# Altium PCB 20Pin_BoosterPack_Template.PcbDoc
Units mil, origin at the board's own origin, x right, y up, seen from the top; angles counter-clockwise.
Board outline 2000 x 1700 mil, 2 copper layers (Top Layer, Bottom Layer), stack 62 mil thick; 2 components, 20 nets, 20 pads, 0 vias.
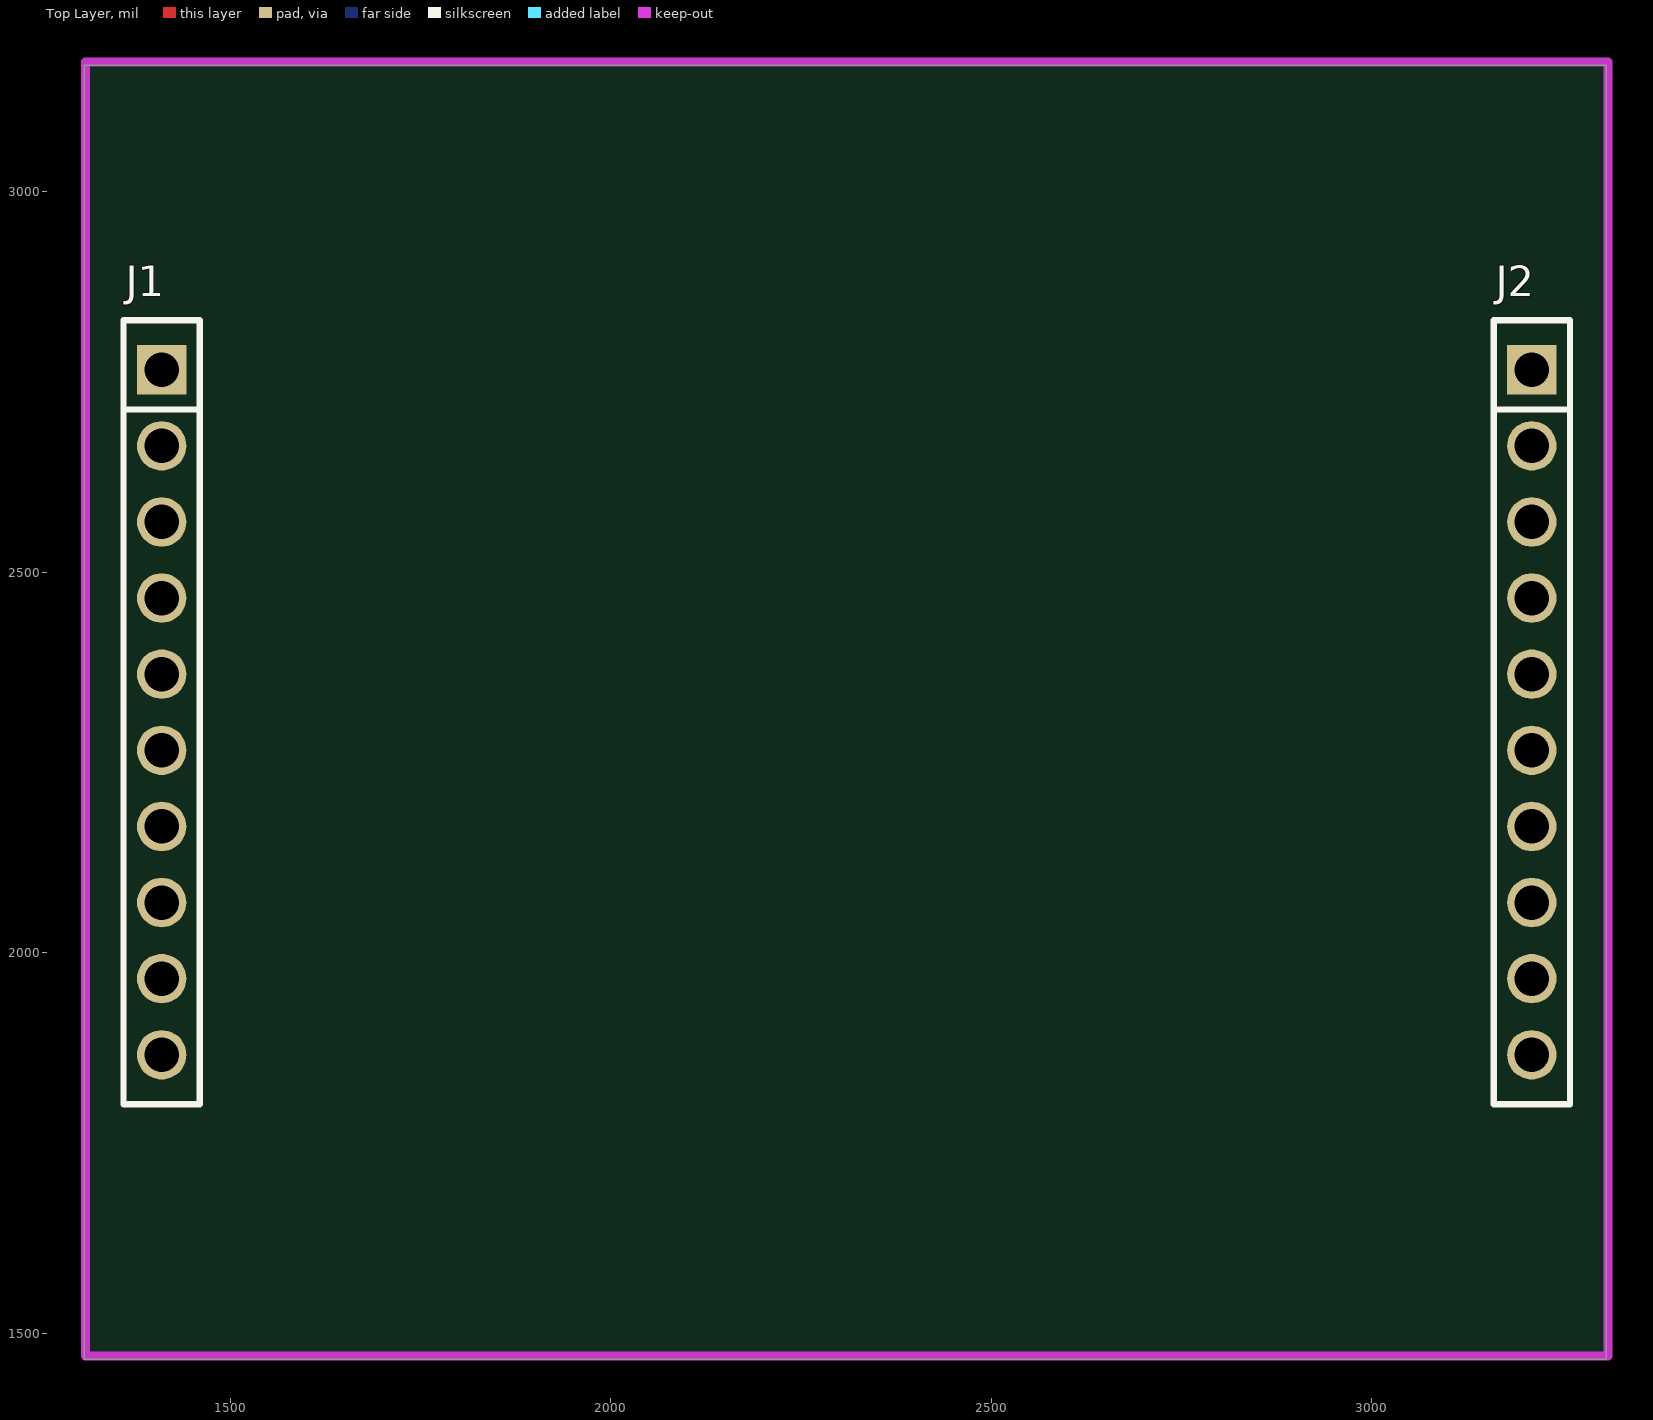
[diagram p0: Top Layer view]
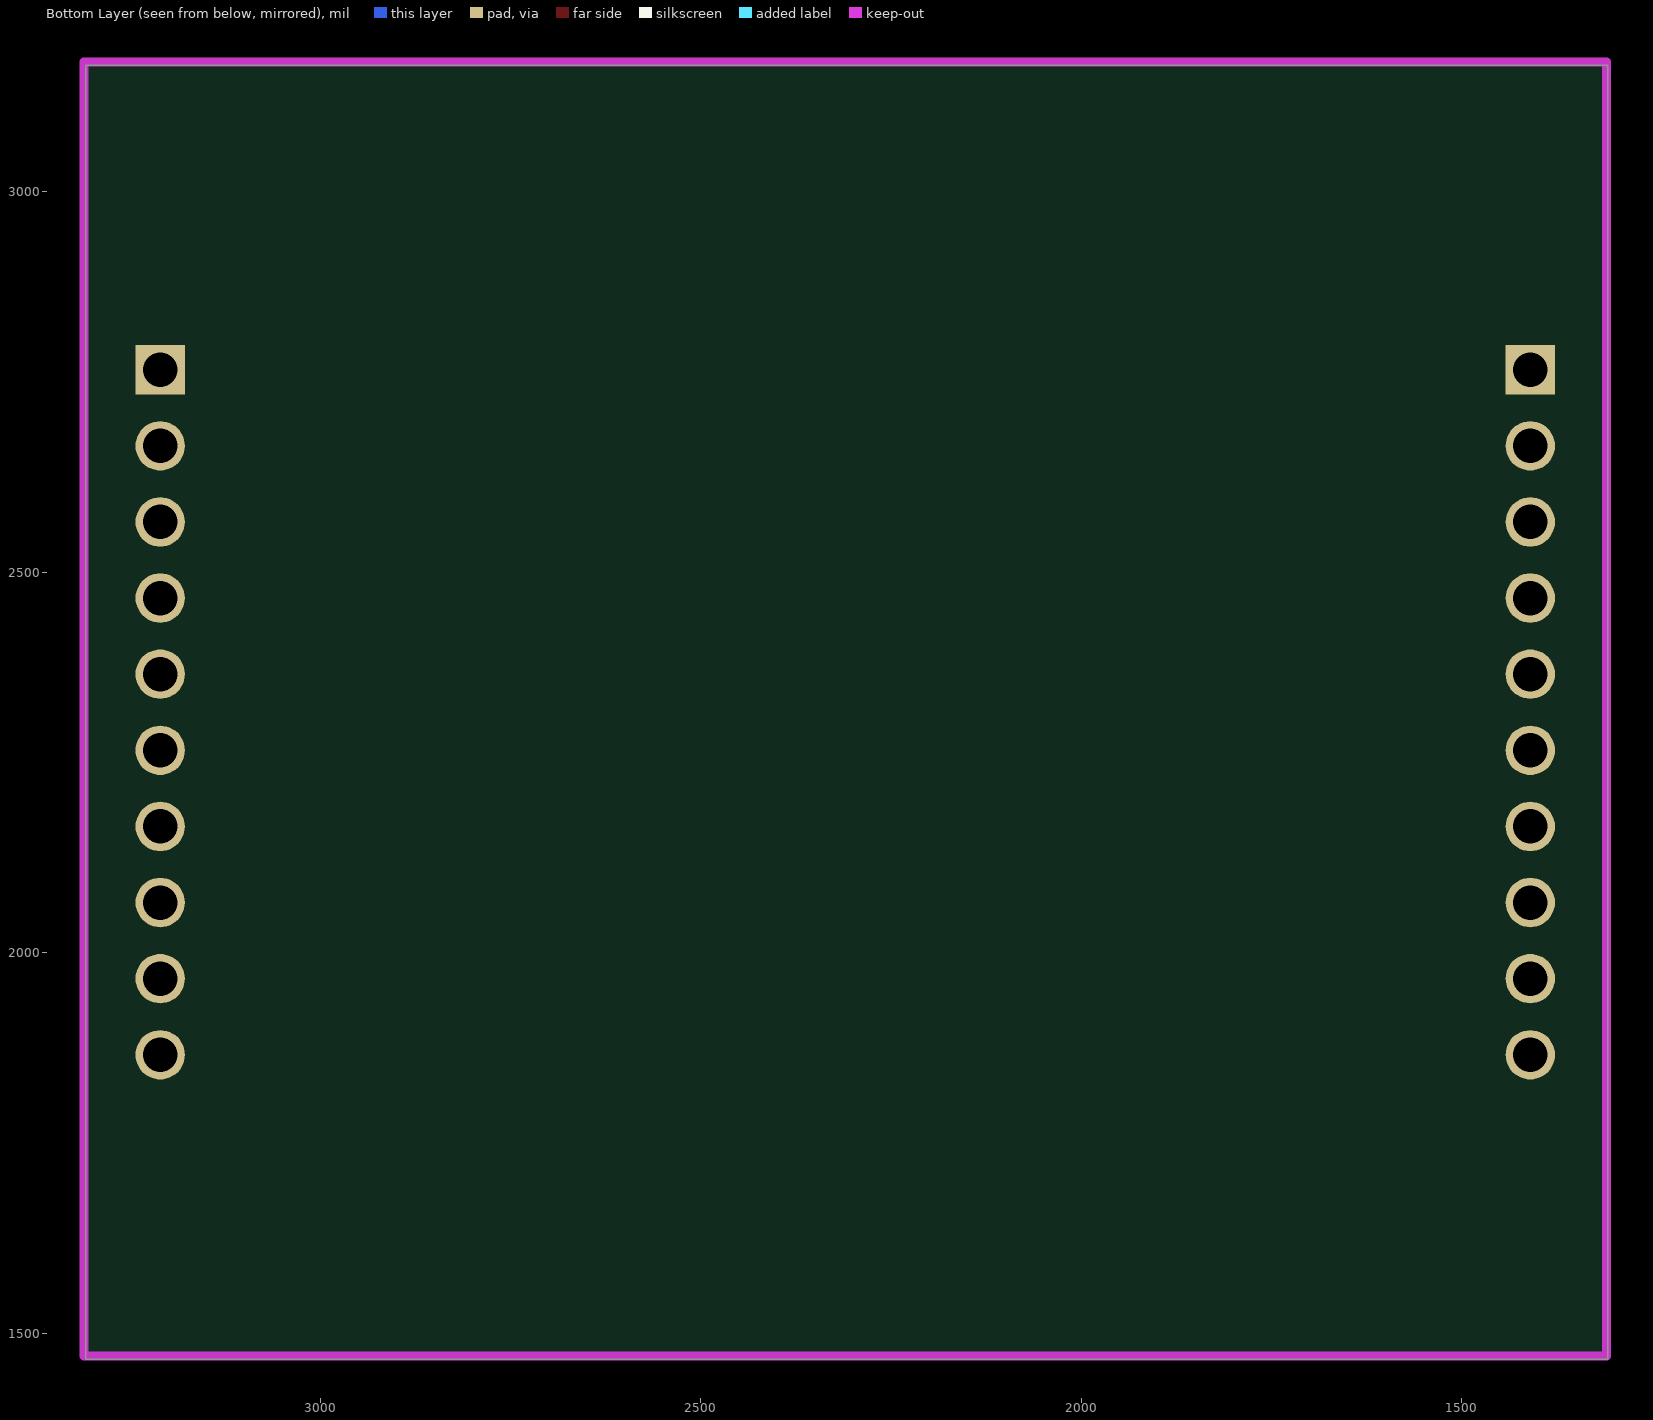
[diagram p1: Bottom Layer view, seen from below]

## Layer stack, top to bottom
Top Layer: signal copper 1.4
Dielectric: core 59.2, FR-4, Dk 4.8
Bottom Layer: signal copper 1.4

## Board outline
1308,1466 3308,1466 3308,3166 1308,3166

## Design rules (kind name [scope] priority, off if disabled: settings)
AcuteAngle [All] p1: minimum=4.50000000000000E+0001 checktracksonly=FALSE
AssemblyTestPointUsage [All] p1: valid=2
Clearance [All] p1: gap=8
ComponentClearance ComponentClearance_Logo [InComponentClass(Logo)] p1: gap=50 collisioncheckmode=3 verticalgap=10 showdistances=FALSE
ComponentClearance ComponentClearance_ScrewToNut [(HasFootprint('NY PMS 440 0025 PH')) vs (HasFootprint('Keystone_1902C'))] p2: gap=5 collisioncheckmode=3 verticalgap=10 showdistances=FALSE
ComponentClearance ComponentClearance_MountingHoles [InComponentClass('Mounting Holes')] p3: gap=250 collisioncheckmode=3 verticalgap=100000 showdistances=FALSE
ComponentClearance ComponentClearance_SmallPassives [HasFootprint('0201*') or HasFootprint('0402*') or HasFootprint('0508') or HasFootprint('0603*') or HasFootprint('0612') or HasFootprint('0805*') or HasFootprint('0815*') or HasFootprint('0830*') or HasFootprint('1206*') or HasFootprint('1210*') or HasFootprint('1808*') or HasFootprint('1812*') or HasFootprint('1825*') or HasFootprint('2010*') or HasFootprint('2220*') or HasFootprint('2225*') or HasFootprint('2512*') or HasFootprint('2728*') or HasFootprint('3518*') vs HasFootprint('0201*') or HasFootprint('0402*') or HasFootprint('0508') or HasFootprint('0603*') or HasFootprint('0612') or HasFootprint('0805*') or HasFootprint('0815*') or HasFootprint('0830*') or HasFootprint('1206*') or HasFootprint('1210*') or HasFootprint('1808*') or HasFootprint('1812*') or HasFootprint('1825*') or HasFootprint('2010*') or HasFootprint('2220*') or HasFootprint('2225*') or HasFootprint('2512*') or HasFootprint('2728*') or HasFootprint('3518*')] p4: gap=20 collisioncheckmode=3 verticalgap=10 showdistances=FALSE
ComponentClearance ComponentClearance_THtoSMT [IsThruComponent vs IsSMTComponent] p5: gap=100 collisioncheckmode=3 verticalgap=100000 showdistances=FALSE
ComponentClearance ComponentClearance_THtoTH [IsThruComponent vs IsThruComponent] p6: gap=118.11 collisioncheckmode=3 verticalgap=100000 showdistances=FALSE
ComponentClearance [All] p7: gap=40 collisioncheckmode=3 verticalgap=10 showdistances=FALSE
DiffPairsRouting [All] p1: maxlimit=100 minlimit=10 mostfreqgap=10 maxuncoupledlength=1000
FabricationTestPointUsage TestPointUsage [All] p1: valid=2 allowmultiple=FALSE
FabricationTestpoint Testpoint [All] p1: side=3 testpointundercomponent=TRUE minsize=40 maxsize=100 preferedsize=60 minholesize=0 maxholesize=40 preferedholesize=32 testpointgrid=1 allowsidetop=TRUE allowsidebottom=TRUE usegrid=TRUE gridtolerance=0.01
FanoutControl Fanout_LCC [IsLCC] p1: bgadir=Out bgaviamode=Centered fanoutstyle=Auto fanoutdirection=Alternating viagrid=1 // Fanout_LCC (Default Rule)
FanoutControl Fanout_BGA [IsBGA] p2: bgadir=Out bgaviamode=Centered fanoutstyle=Auto fanoutdirection=Alternating viagrid=1 // Fanout_BGA (Default Rule)
FanoutControl Fanout_Default [All] p4: bgadir=Out bgaviamode=Centered fanoutstyle=Auto fanoutdirection=Alternating viagrid=1 // Fanout_Default (Default Rule)
FanoutControl Fanout_Small [(CompPinCount < 5)] p5: bgadir=Out bgaviamode=Centered fanoutstyle=Auto fanoutdirection=OutThenIn viagrid=1 // Fanout_Small (Default Rule)
HoleSize [All] p1: absolutevalues=TRUE maxlimit=251 minlimit=8 maxpercent=80.000 minpercent=20.000
MinimumAnnularRing [All] p1: minimumring=9
MinimumSolderMaskSliver MinimumSolderMaskSliver_Logo [InComponentClass('Logo') vs InComponentClass('Logo')] p1: minsoldermaskwidth=0.7
MinimumSolderMaskSliver [All] p2: minsoldermaskwidth=4
PolygonConnect [All] p1: connectstyle=Relief reliefconductorwidth=10 reliefentries=4 polygonreliefangle="90 Angle" airgapwidth=10
RoutingVias [All] p1: holewidth=25 width=40 viastyle="Through Hole" minholewidth=28 minwidth=50 maxholewidth=28 maxwidth=50
SMDToCorner [All] p1: distance=30000
SilkToSilkClearance [All] p1: silktosilkclearance=5
SilkscreenOverComponentPads [All] p1: minsilkscreentomaskgap=5
SolderMaskExpansion [All] p1: expansion=3
Width [All] p1: maxlimit=8 minlimit=8 preferedwidth=8
15 further rules are at their usual default settings.

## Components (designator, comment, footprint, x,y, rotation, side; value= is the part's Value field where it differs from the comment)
J1 "SSW-110-23-F-S" CONN_SSW-110-23-F-S 1409.99,2765.82 r90 top
J2 "SSW-110-23-F-S" CONN_SSW-110-23-F-S 3209.99,2765.82 r90 top

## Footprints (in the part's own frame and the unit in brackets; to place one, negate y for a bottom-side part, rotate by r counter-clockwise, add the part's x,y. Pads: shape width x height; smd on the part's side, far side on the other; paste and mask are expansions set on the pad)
CONN_SSW-110-23-F-S [mm] "SAMTEC"
  rect 1.65x1.65 hole 1.15: 1(0,0)
  round 1.65 hole 1.15: 2(-2.54,0) 3(-5.08,0) 4(-7.62,0) 5(-10.16,0) 6(-12.7,0) 7(-15.24,0) 8(-17.78,0) 9(-20.32,0) 10(-22.86,0)
  silkscreen extent -24.51,-1.27 1.65,1.27, body extent -24.43,-1.27 1.57,1.27, height 8.59

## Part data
J1 J2: "Connector, Receptacle, 100mil, 10x1, Gold plated, TH"

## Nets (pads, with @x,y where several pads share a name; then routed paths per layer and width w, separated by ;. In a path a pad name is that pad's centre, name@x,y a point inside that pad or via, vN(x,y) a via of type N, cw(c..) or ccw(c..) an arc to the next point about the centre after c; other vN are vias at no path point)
+3.3V: J1.1
GND: J2.1
J1.2: J1.2
J1.3: J1.3
J1.4: J1.4
J1.5: J1.5
J1.6: J1.6
J1.7: J1.7
J1.8: J1.8
J1.9: J1.9
J1.10: J1.10
J2.2: J2.2
J2.3: J2.3
J2.4: J2.4
J2.5: J2.5
J2.6: J2.6
J2.7: J2.7
J2.8: J2.8
J2.9: J2.9
J2.10: J2.10

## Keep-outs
Keep-Out Layer:
  lines w11.81: 1310,1470 3310,1470 3310,3170 1310,3170 1310,1470

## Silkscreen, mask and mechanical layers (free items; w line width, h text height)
Bottom Overlay:
  rectangle: 638,150 938,250
M2 Board Dimensions:
  rectangle: 124.5,-410.5 499.5,-285.5
  rectangle: -0.5,-285.5 124.5,-160.5
  lines w10: -0.5,-475.5 -0.5,-455.5 ; 59.5,-485.5 -0.5,-465.5 ; 59.5,-445.5 -0.5,-465.5 ; 223.58,-465.5 -0.5,-465.5 ; 775.42,-465.5 999.5,-465.5 ; 939.5,-485.5 999.5,-465.5 ; 939.5,-445.5 999.5,-465.5 ; 999.5,-475.5 999.5,-455.5
  text "1000 (mil)" at 233.58,-501.49 h60
M9 Title Sheet:
  drawing of 18 lines, arcs and shapes, not listed
Drill Drawing:
  text ".LEGEND" at 3508,1666 h60
  text "Drill Drawing." at 3508,1566 h60

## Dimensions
1360,3170 to 1359.18,1470 on M1 Board Outline
1310,1460 to 3310,1470 on M1 Board Outline
0,0 to 3308,1466 on M2 Board Dimensions
0,0 to 1308,3166 on M2 Board Dimensions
